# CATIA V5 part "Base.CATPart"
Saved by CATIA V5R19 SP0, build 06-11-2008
Part number: Base
Bounding box of the stored display mesh (mm): x -155 to 155, y -320 to 530, z -360 to 40
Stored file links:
  G:\EU_thinkMotion\CFAO_2010\MMS_groupe3\MMS_groupe3\rdalborgo\rdalborgo\Base.CATPart
  G:\EU_thinkMotion\CFAO_2010\MMS_groupe3\MMS_groupe3\rdalborgo\rdalborgo\rdalborgo.CATProduct
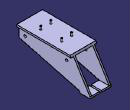
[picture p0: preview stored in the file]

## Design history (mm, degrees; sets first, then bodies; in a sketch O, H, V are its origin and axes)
External parameters (linked from other documents)
  `External.Largeur bielle` = 210 mm
  External.entraxe = 500 mm
Set1
  Plane1: linked copy from another document
  Point1 to Point3: linked copy from another document
  Plane2 to Plane4: linked copy from another document
  Point4 "A bielle": linked copy from another document
  Point5 "B bielle": linked copy from another document
Body1 (main body)
  Sketch1 on Plane1, origin (0, 0, 0), H (0, 1, 0), V (0, 0, 1)
    point P1 (320, 0)
    line L1 (320, 0) -> (-320, 0)
    point P2 (-320, 0)
    line L2 (-320, 0) -> (-320, -150)
    line L3 (-320, -150) -> (410, -340)
    line L4 (410, -340) -> (410, -360)
    line L5 (410, -360) -> (530, -360)
    line L6 (530, -360) -> (530, -340)
    line L7 (530, -340) -> (320, 0)
    reference projected point E1 (470, -360) from Point2
    reference projected point E2 (-320, 0) from Point3
    reference projected point E3 (320, 0) from Point1
    reference projected point E4 (470, -360) from Point2
    length L4 = 20
    length L5 = 120
    distance L6 E4 = 60
    length L2 = 150
    length L6 = 20
    horizontal: L1 H, L5 H
    vertical: L2 V, L4 V, L6 V
    coincidence: L5 E1, P2 E2, P1 E3
  Sketch2 on Plane2, origin (0, 0, 0), H (-1, 0, 0), V (0, 0, 1)
    point P1 (-155, 0)
    line L1 (-155, 0) -> (155, 0)
    line L2 (155, 0) -> (155, -20)
    line L3 (155, -20) -> (125, -20)
    line L4 (125, -20) -> (125, -360)
    line L5 (125, -360) -> (10, -360)
    line L6 (10, -360) -> (10, -340)
    line L7 (10, -340) -> (105, -340)
    line L8 (105, -340) -> (105, -20)
    point P9 (105, -20)
    line L9 (105, -20) -> (-105, -20)
    line L10 (-105, -20) -> (-105, -340)
    line L11 (-105, -340) -> (-10, -340)
    line L12 (-10, -340) -> (-10, -360)
    line L13 (-10, -360) -> (-125, -360)
    line L14 (-125, -360) -> (-125, -20)
    line L15 (-125, -20) -> (-155, -20)
    line L16 (-155, -20) -> (-155, 0)
    point P17 (-155, 0)
    reference intersected line E1 through (0, 0) direction (-1, 0) from Plane3
    reference intersected line E2 through (0, -360) direction (-1, 0) from Plane4
    reference projected point E3 (0, -360) from Point2
    distance L9 L1 = 20
    distance L10 L14 = 20
    distance L8 L4 = 20
    distance L16 L14 = 30
    distance L4 L2 = 30
    distance L10 L8 = 210 {= `External.Largeur bielle`}
    distance L7 L5 = 20
    distance L11 L13 = 20
    distance L12 L10 = 95 {= `External.Largeur bielle` /2-10mm}
    distance L12 L6 = 20
    distance L12 E3 = 10
    horizontal: L1 H, L3 H, L5 H, L7 H, L9 H, L11 H, L13 H, L15 H
    vertical: L2 V, L4 V, L6 V, L8 V, L10 V, L12 V, L14 V, L16 V
    coincidence: P9 L3, P1 P17, L15 L9, L11 L7, L1 E1, L5 E2
  SolidCombine1: FirstComponentProfile Sketch2, FirstComponentDirection Sketch2, SecondComponentProfile Sketch1, SecondComponentDirection Sketch1
  Sketch3 on Plane1, origin (0, 0, 0), H (0, 1, 0), V (0, 0, 1)
    circle A1 centre (-250, -100) radius 15
    point P1 (-250, -100)
    circle A2 centre (250, -100) radius 15
    point P2 (250, -100)
    reference projected point E1 (-250, -100) from Point4
    reference projected point E2 (250, -100) from Point5
    radius A1 = 15
    radius A2 = 15
    coincidence: P1 E1, P2 E2
  Pocket1: profile Sketch3, direction (-1, 0, 0), length 210 {= `External.Largeur bielle`}, mirrored extent
  Sketch4 on face of SolidCombine1 from Sketch2.L9, origin (-65.5603, 186.4044, -20), H (1, 0, 0), V (0, -1, 0)
    point P1 (125.5603, 61.4044)
    reference intersected line E1 through (65.5603, 0) direction (0, 1) from Plane1
    reference intersected line E2 through (0, 186.4044) direction (1, 0) from Plane2
    distance P1 E1 = 60
    distance P1 E2 = 125 {= External.entraxe /4}
  Hole1: placed by Sketch4, at (60, 125, -20) direction (0, 0, 1), diameter 20, through (limit type 3)
  RectPattern1: of Hole1, direction 1 instances 2, spacing 120, along face of SolidCombine1 from Sketch2.L9 reversed, direction 2 instances 2, spacing 250 {= External.entraxe /2}, along face of SolidCombine1 from Sketch2.L9
Body2 "Vis 1"
  Sketch5 on face of SolidCombine1 from Sketch2.L9, origin (0, 0, -20), H (1, 0, 0), V (0, -1, 0)
    circle A1 centre (-60, -125) radius 10
    reference projected circle E1 centre (-60, -125) radius 10 from edge [face of RectPattern1 | face of SolidCombine1 from Sketch2.L9]
    radius A1 = 10
    concentricity: A1 E1
  Pad1: profile Sketch5, direction (0, 0, 1), length 60
  Chamfer1: length 4, angle 45, on edge [end face of Pad1 | face of Pad1 from Sketch5.A1]
  Sketch6 on start face of Pad1, origin (0, 0, -20), H (1, 0, 0), V (0, -1, 0)
    circle A1 centre (-60, -125) radius 14
    reference projected circle E1 centre (-60, -125) radius 10 from edge [face of Pad1 from Sketch5.A1 | start face of Pad1]
    radius A1 = 14
    concentricity: A1 E1
  Pad2: profile Sketch6, direction (0, 0, -1), length 2
  Sketch7 on end face of Pad2, origin (0, 0, -22), H (1, 0, 0), V (0, -1, 0)
    point P1 (-60, -125)
    point P2 (-65.7735, -135)
    point P3 (-54.2265, -135)
    point P4 (-48.453, -125)
    point P5 (-54.2265, -115)
    point P6 (-65.7735, -115)
    point P7 (-71.547, -125)
    point P8 (-60, -135)
    line L1 (-65.7735, -135) -> (-54.2265, -135)
    line L2 (-54.2265, -135) -> (-48.453, -125)
    line L3 (-48.453, -125) -> (-54.2265, -115)
    line L4 (-54.2265, -115) -> (-65.7735, -115)
    line L5 (-65.7735, -115) -> (-71.547, -125)
    line L6 (-71.547, -125) -> (-65.7735, -135)
    construction line L7 (-60, -125) -> (-60, -135)
    construction circle A1 centre (-60, -125) radius 11.547
    construction arc A2 centre (-65.7735, -115) radius 11.547 from (-54.2265, -115) to (-71.547, -125) cw
    construction arc A3 centre (-54.2265, -135) radius 11.547 from (-48.453, -125) to (-65.7735, -135) ccw
    reference projected circle E1 centre (-60, -125) radius 14 from edge [face of Pad2 from Sketch6.A1 | end face of Pad2]
    distance L1 L4 = 20
    coincidence: A1 P2, A1 P3, A1 P4, A1 P5, A1 P6, A1 P7, A2 P1, A3 P1
    midpoint: P8 L1
    concentricity: P1 E1
  Pad3: profile Sketch7, direction (0, 0, -1), length 8
Body3 "Vis 2"
  Sketch8 on face of SolidCombine1 from Sketch2.L9, origin (0, 0, -20), H (1, 0, 0), V (0, -1, 0)
    circle A1 centre (60, -125) radius 10
    reference projected circle E1 centre (60, -125) radius 10 from edge [face of Hole1 | face of SolidCombine1 from Sketch2.L9]
    radius A1 = 10
    concentricity: A1 E1
  Pad4: profile Sketch8, direction (0, 0, 1), length 60
  Chamfer2: length 4, angle 45, on edge [end face of Pad4 | face of Pad4 from Sketch8.A1]
  Sketch9 on start face of Pad4, origin (0, 0, -20), H (1, 0, 0), V (0, -1, 0)
    circle A1 centre (60, -125) radius 14
    reference projected circle E1 centre (60, -125) radius 10 from edge [face of Pad4 from Sketch8.A1 | start face of Pad4]
    radius A1 = 14
    concentricity: A1 E1
  Pad5: profile Sketch9, direction (0, 0, -1), length 2
  Sketch10 on end face of Pad5, origin (0, 0, -22), H (1, 0, 0), V (0, -1, 0)
    point P1 (60, -125)
    point P2 (54.2265, -135)
    point P3 (65.7735, -135)
    point P4 (71.547, -125)
    point P5 (65.7735, -115)
    point P6 (54.2265, -115)
    point P7 (48.453, -125)
    point P8 (60, -135)
    line L1 (54.2265, -135) -> (65.7735, -135)
    line L2 (65.7735, -135) -> (71.547, -125)
    line L3 (71.547, -125) -> (65.7735, -115)
    line L4 (65.7735, -115) -> (54.2265, -115)
    line L5 (54.2265, -115) -> (48.453, -125)
    line L6 (48.453, -125) -> (54.2265, -135)
    construction line L7 (60, -125) -> (60, -135)
    construction circle A1 centre (60, -125) radius 11.547
    construction arc A2 centre (54.2265, -115) radius 11.547 from (65.7735, -115) to (48.453, -125) cw
    construction arc A3 centre (65.7735, -135) radius 11.547 from (71.547, -125) to (54.2265, -135) ccw
    reference projected circle E1 centre (60, -125) radius 14 from edge [face of Pad5 from Sketch9.A1 | end face of Pad5]
    distance L1 L4 = 20
    coincidence: A1 P2, A1 P3, A1 P4, A1 P5, A1 P6, A1 P7, A2 P1, A3 P1
    midpoint: P8 L1
    concentricity: P1 E1
  Pad6: profile Sketch10, direction (0, 0, -1), length 8
Body4 "Vis 3"
  Sketch11 on face of SolidCombine1 from Sketch2.L9, origin (0, 0, -20), H (1, 0, 0), V (0, -1, 0)
    circle A1 centre (-60, 125) radius 10
    reference projected circle E1 centre (-60, 125) radius 10 from edge [face of RectPattern1 | face of SolidCombine1 from Sketch2.L9]
    radius A1 = 10
    concentricity: A1 E1
  Pad7: profile Sketch11, direction (0, 0, 1), length 60
  Chamfer3: length 4, angle 45, on edge [end face of Pad7 | face of Pad7 from Sketch11.A1]
  Sketch12 on start face of Pad7, origin (0, 0, -20), H (1, 0, 0), V (0, -1, 0)
    circle A1 centre (-60, 125) radius 14
    reference projected circle E1 centre (-60, 125) radius 10 from edge [face of Pad7 from Sketch11.A1 | start face of Pad7]
    radius A1 = 14
    concentricity: A1 E1
  Pad8: profile Sketch12, direction (0, 0, -1), length 2
  Sketch13 on end face of Pad8, origin (0, 0, -22), H (1, 0, 0), V (0, -1, 0)
    point P1 (-60, 125)
    point P2 (-65.7735, 115)
    point P3 (-54.2265, 115)
    point P4 (-48.453, 125)
    point P5 (-54.2265, 135)
    point P6 (-65.7735, 135)
    point P7 (-71.547, 125)
    point P8 (-60, 115)
    line L1 (-65.7735, 115) -> (-54.2265, 115)
    line L2 (-54.2265, 115) -> (-48.453, 125)
    line L3 (-48.453, 125) -> (-54.2265, 135)
    line L4 (-54.2265, 135) -> (-65.7735, 135)
    line L5 (-65.7735, 135) -> (-71.547, 125)
    line L6 (-71.547, 125) -> (-65.7735, 115)
    construction line L7 (-60, 125) -> (-60, 115)
    construction circle A1 centre (-60, 125) radius 11.547
    construction arc A2 centre (-65.7735, 135) radius 11.547 from (-54.2265, 135) to (-71.547, 125) cw
    construction arc A3 centre (-54.2265, 115) radius 11.547 from (-48.453, 125) to (-65.7735, 115) ccw
    reference projected circle E1 centre (-60, 125) radius 14 from edge [face of Pad8 from Sketch12.A1 | end face of Pad8]
    distance L1 L4 = 20
    coincidence: A1 P2, A1 P3, A1 P4, A1 P5, A1 P6, A1 P7, A2 P1, A3 P1
    midpoint: P8 L1
    concentricity: P1 E1
  Pad9: profile Sketch13, direction (0, 0, -1), length 8
Body5 "Vis 4"
  Sketch14 on face of SolidCombine1 from Sketch2.L9, origin (0, 0, -20), H (1, 0, 0), V (0, -1, 0)
    circle A1 centre (60, 125) radius 10
    reference projected circle E1 centre (60, 125) radius 10 from edge [face of RectPattern1 | face of SolidCombine1 from Sketch2.L9]
    radius A1 = 10
    concentricity: A1 E1
  Pad10: profile Sketch14, direction (0, 0, 1), length 60
  Chamfer4: length 4, angle 45, on edge [end face of Pad10 | face of Pad10 from Sketch14.A1]
  Sketch15 on start face of Pad10, origin (0, 0, -20), H (1, 0, 0), V (0, -1, 0)
    circle A1 centre (60, 125) radius 14
    reference projected circle E1 centre (60, 125) radius 10 from edge [face of Pad10 from Sketch14.A1 | start face of Pad10]
    radius A1 = 14
    concentricity: A1 E1
  Pad11: profile Sketch15, direction (0, 0, -1), length 2
  Sketch16 on end face of Pad11, origin (0, 0, -22), H (1, 0, 0), V (0, -1, 0)
    point P1 (60, 125)
    point P2 (54.2265, 115)
    point P3 (65.7735, 115)
    point P4 (71.547, 125)
    point P5 (65.7735, 135)
    point P6 (54.2265, 135)
    point P7 (48.453, 125)
    point P8 (60, 115)
    line L1 (54.2265, 115) -> (65.7735, 115)
    line L2 (65.7735, 115) -> (71.547, 125)
    line L3 (71.547, 125) -> (65.7735, 135)
    line L4 (65.7735, 135) -> (54.2265, 135)
    line L5 (54.2265, 135) -> (48.453, 125)
    line L6 (48.453, 125) -> (54.2265, 115)
    construction line L7 (60, 125) -> (60, 115)
    construction circle A1 centre (60, 125) radius 11.547
    construction arc A2 centre (54.2265, 135) radius 11.547 from (65.7735, 135) to (48.453, 125) cw
    construction arc A3 centre (65.7735, 115) radius 11.547 from (71.547, 125) to (54.2265, 115) ccw
    reference projected circle E1 centre (60, 125) radius 14 from edge [face of Pad11 from Sketch15.A1 | end face of Pad11]
    distance L1 L4 = 20
    coincidence: A1 P2, A1 P3, A1 P4, A1 P5, A1 P6, A1 P7, A2 P1, A3 P1
    midpoint: P8 L1
    concentricity: P1 E1
  Pad12: profile Sketch16, direction (0, 0, -1), length 8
